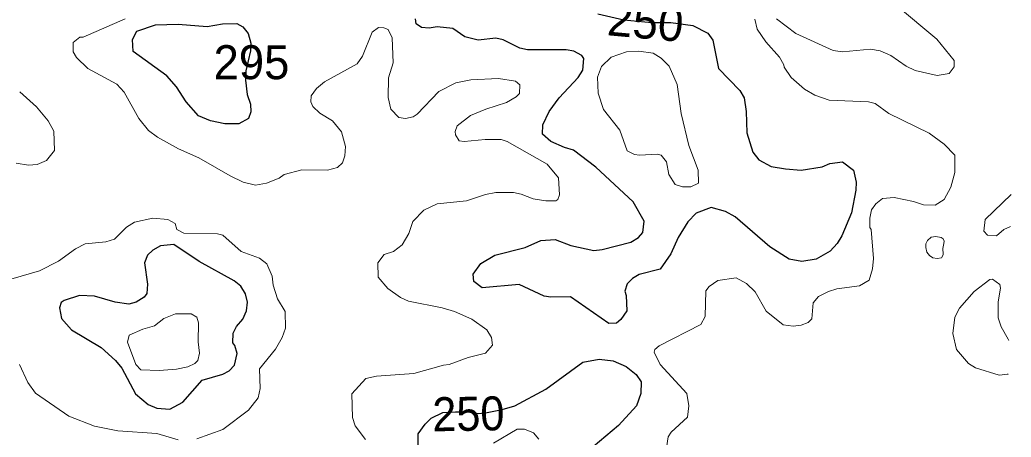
# Model space of a CAD drawing. Extents: x 763.2 to 816.8, y 7896.5 to 7952.7.
# Drawn here: x 811.377 to 816.045, y 7905.868 to 7907.832 of the extents above; entities that cross this region are included whole.
import ezdxf
from ezdxf.enums import TextEntityAlignment as Align

# ---------------------------------------------------------------- set-up
doc = ezdxf.new("R2010")
doc.units = 0
doc.header["$LTSCALE"] = 0.064
doc.layers.add('1', color=7, linetype='Continuous', lineweight=25)
doc.layers.add('2', color=7, linetype='Continuous', lineweight=13)
doc.layers.add('21', color=7, linetype='Continuous')
doc.layers.add('61', color=7, linetype='Continuous')

msp = doc.modelspace()

# ---------------------------------------------------------------- linework, layer by layer
at = {"layer": '1'}
for points in [[(815.1546, 7907.1394), (815.1905, 7907.156), (815.2505, 7907.164), (815.3026, 7907.1252), (815.3146, 7907.068), (815.3129, 7907.0303), (815.2921, 7906.9243), (815.2477, 7906.8148), (815.2254, 7906.7791), (815.193, 7906.7436), (815.1264, 7906.706), (815.0592, 7906.6943), (815, 7906.7063), (814.9089, 7906.7636), (814.7444, 7906.9045), (814.7, 7906.9307), (814.6327, 7906.9487), (814.5617, 7906.9216), (814.5226, 7906.8815), (814.4766, 7906.8075), (814.4424, 7906.7304), (814.3918, 7906.659), (814.2935, 7906.6329), (814.2614, 7906.6152), (814.2359, 7906.5899), (814.2254, 7906.5552), (814.2316, 7906.5349), (814.2347, 7906.4625), (814.2064, 7906.4211), (814.1859, 7906.4047), (814.1495, 7906.4035), (813.9702, 7906.5279), (813.8768, 7906.5266), (813.8448, 7906.5322), (813.7271, 7906.5857), (813.554, 7906.5714), (813.5151, 7906.5998), (813.5105, 7906.6358), (813.5478, 7906.6857), (813.6131, 7906.725), (813.7567, 7906.7611), (813.8299, 7906.794), (813.8977, 7906.7974), (813.9713, 7906.77), (814.0798, 7906.7469), (814.1182, 7906.7504), (814.2531, 7906.7858), (814.2898, 7906.8071), (814.3106, 7906.8315), (814.3169, 7906.8846), (814.2647, 7906.9754), (814.0892, 7907.139), (813.9831, 7907.2187), (813.9408, 7907.2306), (813.8762, 7907.2597), (813.8377, 7907.2942), (813.8395, 7907.3383), (813.8691, 7907.401), (813.9167, 7907.4655), (814.0053, 7907.5606), (814.0273, 7907.5958), (814.0328, 7907.6507), (814.0236, 7907.6647), (813.9858, 7907.6847), (813.949, 7907.6901), (813.7675, 7907.6903), (813.7305, 7907.699), (813.6532, 7907.7376), (813.6178, 7907.7457), (813.5349, 7907.7363), (813.4714, 7907.7525), (813.4163, 7907.7905), (813.3417, 7907.7984), (813.3047, 7907.7921), (813.268, 7907.7957), (813.2422, 7907.8133), (813.239, 7907.837)], [(814.0977, 7907.8609), (814.2211, 7907.8314), (814.3532, 7907.8196), (814.4415, 7907.8194), (814.545, 7907.8057)], [(814.545, 7907.8057), (814.617, 7907.7692), (814.6393, 7907.7369), (814.6658, 7907.6031), (814.7669, 7907.4999), (814.7872, 7907.4642)], [(814.7872, 7907.4642), (814.7968, 7907.4009), (814.8004, 7907.2999), (814.8275, 7907.2091), (814.8563, 7907.1726), (814.9137, 7907.1424), (814.9813, 7907.13), (815.056, 7907.1249), (815.1546, 7907.1394)], [(813.252, 7905.8034), (813.2527, 7905.8844), (813.285, 7905.9298), (813.3142, 7905.9574), (813.3692, 7905.9836), (813.4279, 7905.9878), (813.4839, 7905.9865), (813.5386, 7905.9789), (813.5768, 7905.984), (813.6474, 7905.9979), (813.7069, 7906.0154), (813.8531, 7906.0939), (814.0273, 7906.2204), (814.1043, 7906.2355), (814.1699, 7906.2271), (814.231, 7906.2012), (814.2793, 7906.1633), (814.3023, 7906.1288), (814.3007, 7906.073), (814.28, 7906.0148), (814.1959, 7905.9223), (814.076, 7905.8218)]]:
    msp.add_lwpolyline(points, dxfattribs=at)
for points in [[(812.1223, 7907.8115), (812.2595, 7907.8002), (812.3302, 7907.8134), (812.398, 7907.8146), (812.4266, 7907.7989), (812.4513, 7907.7679), (812.4646, 7907.7229), (812.4634, 7907.6859), (812.4415, 7907.5925), (812.4387, 7907.5484), (812.4469, 7907.4804), (812.4629, 7907.4344), (812.4645, 7907.3997), (812.4539, 7907.3684), (812.4071, 7907.3431), (812.3425, 7907.3429), (812.275, 7907.3566), (812.2173, 7907.3803), (812.1594, 7907.4453), (812.1148, 7907.5166), (812.0682, 7907.5692), (811.9103, 7907.6832), (811.9073, 7907.7399), (811.9279, 7907.7787), (812.0147, 7907.8081)], [(812.4485, 7906.5025), (812.4399, 7906.542), (812.4167, 7906.578), (812.386, 7906.6037), (812.2208, 7906.6953), (812.1022, 7906.7745), (812.0387, 7906.7676), (812.0026, 7906.7478), (811.9771, 7906.7252), (811.9639, 7906.6885), (811.9784, 7906.5873), (811.9751, 7906.5436), (811.9614, 7906.5262), (811.925, 7906.504), (811.8898, 7906.4939), (811.8258, 7906.5036), (811.7277, 7906.5312), (811.6581, 7906.5347), (811.5852, 7906.5113), (811.5708, 7906.501), (811.563, 7906.4772), (811.5729, 7906.4265), (811.6202, 7906.3737), (811.7593, 7906.2903), (811.8269, 7906.2292), (811.8577, 7906.193), (811.921, 7906.0716), (811.9808, 7906.0211), (812.0213, 7906.0037), (812.0837, 7905.999), (812.1449, 7906.0323), (812.2356, 7906.1356), (812.3325, 7906.1637), (812.3629, 7906.1799), (812.3871, 7906.2072), (812.4006, 7906.2622), (812.3891, 7906.2996), (812.3791, 7906.3122), (812.3813, 7906.3572), (812.3965, 7906.389), (812.4274, 7906.4237), (812.4436, 7906.4631)]]:
    msp.add_lwpolyline(points, close=True, dxfattribs=at)
at = {"layer": '2'}
for points in [[(815.5054, 7907.8989), (815.6938, 7907.7415), (815.7764, 7907.6401), (815.7764, 7907.6104), (815.7521, 7907.5789), (815.6956, 7907.5702), (815.5931, 7907.5929), (815.5502, 7907.6147), (815.4776, 7907.6645), (815.4283, 7907.6866), (815.3828, 7907.6932), (815.2497, 7907.682), (815.2066, 7907.6872), (815.0311, 7907.767), (814.9402, 7907.8368)], [(813.2785, 7906.9355), (813.342, 7906.9665), (813.4795, 7906.9802), (813.5691, 7907.0099), (813.6177, 7907.0195), (813.7014, 7907.0191), (813.7377, 7907.0122), (813.7939, 7906.9902), (813.8538, 7906.9802), (813.9002, 7906.9802), (813.9102, 7906.9865), (813.9177, 7907.0087), (813.9128, 7907.089), (813.8596, 7907.1529), (813.6709, 7907.2592), (813.6426, 7907.2689), (813.5677, 7907.2693), (813.4691, 7907.2595), (813.4446, 7907.2633), (813.4282, 7907.2908), (813.4266, 7907.3068), (813.4366, 7907.3333), (813.4992, 7907.3815), (813.5711, 7907.4123), (813.6683, 7907.443), (813.7139, 7907.4702), (813.7287, 7907.486), (813.7317, 7907.5265), (813.7109, 7907.5433), (813.6301, 7907.5553), (813.4998, 7907.5492), (813.4298, 7907.5354), (813.3497, 7907.4949), (813.2473, 7907.3877), (813.2288, 7907.3754), (813.1921, 7907.3681), (813.1606, 7907.3718), (813.1241, 7907.4108), (813.111, 7907.467), (813.1123, 7907.5588), (813.1338, 7907.63), (813.1304, 7907.7476), (813.1106, 7907.7867), (813.091, 7907.795), (813.0658, 7907.7952), (813.0354, 7907.7738), (812.9905, 7907.6615), (812.965, 7907.625), (812.8105, 7907.5397), (812.7731, 7907.5085), (812.7478, 7907.4741), (812.7462, 7907.4453), (812.7556, 7907.4242), (812.7899, 7907.3934), (812.8484, 7907.3559), (812.8912, 7907.3052), (812.9102, 7907.2365), (812.9069, 7907.1915), (812.8955, 7907.1594), (812.8731, 7907.1375), (812.8249, 7907.1248), (812.704, 7907.1263), (812.6212, 7907.1033), (812.5974, 7907.087), (812.5376, 7907.0635), (812.4859, 7907.0542), (812.4279, 7907.0686), (812.3674, 7907.0971), (812.2201, 7907.1822), (812.1237, 7907.2246), (812.0251, 7907.2805), (811.9823, 7907.3115), (811.9366, 7907.3684), (811.8684, 7907.4912), (811.8334, 7907.5294), (811.6965, 7907.6026), (811.6427, 7907.6544), (811.628, 7907.6809), (811.6281, 7907.7246), (811.6599, 7907.7506), (811.6753, 7907.7511), (811.8724, 7907.8365)], [(814.8381, 7907.8355), (814.8487, 7907.7874), (814.8891, 7907.7284), (814.9531, 7907.6555), (814.9741, 7907.6207), (814.9753, 7907.6086), (815.0086, 7907.5609), (815.0712, 7907.5052), (815.1198, 7907.4778), (815.1875, 7907.4538), (815.3733, 7907.4468), (815.4044, 7907.4386), (815.4682, 7907.3906), (815.6589, 7907.2986), (815.7294, 7907.2474), (815.7792, 7907.1958), (815.7795, 7907.1134), (815.76, 7907.0442), (815.7293, 7906.9858)], [(811.3762, 7907.4936), (811.4553, 7907.4227), (811.5096, 7907.3572), (811.5364, 7907.308), (811.5398, 7907.2166), (811.5015, 7907.1693), (811.4586, 7907.1514), (811.4181, 7907.1478), (811.3589, 7907.1576)], [(815.4386, 7906.9916), (815.4079, 7906.9663), (815.3872, 7906.9372), (815.3788, 7906.8989), (815.3788, 7906.8551), (815.3853, 7906.8456), (815.3969, 7906.7092), (815.392, 7906.6603), (815.3752, 7906.6073), (815.3304, 7906.5799), (815.2244, 7906.5658), (815.1842, 7906.5541), (815.1367, 7906.5303), (815.1128, 7906.5), (815.106, 7906.4245), (815.0884, 7906.4068), (815.0553, 7906.3948), (815.0179, 7906.3902), (814.9706, 7906.3964), (814.8902, 7906.4613), (814.8392, 7906.5515), (814.7976, 7906.5917), (814.7496, 7906.6182), (814.6629, 7906.6056), (814.6224, 7906.5769), (814.6064, 7906.5563), (814.6036, 7906.4353), (814.5829, 7906.3987), (814.3874, 7906.2972), (814.3665, 7906.2807), (814.3636, 7906.2674), (814.3918, 7906.2096), (814.5177, 7906.074), (814.5273, 7906.0154), (814.5209, 7905.9622), (814.4433, 7905.8914), (814.429, 7905.87), (814.4223, 7905.8173)], [(815.7293, 7906.9858), (815.6874, 7906.9592), (815.6313, 7906.9606), (815.5851, 7906.977), (815.4931, 7906.9965), (815.4386, 7906.9916)], [(816.0421, 7906.859), (816.0099, 7906.845), (815.9756, 7906.8162), (815.9334, 7906.8183), (815.9151, 7906.837), (815.9224, 7906.8916), (816.0444, 7907.0097), (816.0446, 7907.0099)], [(812.2093, 7905.8599), (812.3324, 7905.9041), (812.4528, 7905.9951), (812.4993, 7906.0525), (812.5076, 7906.0977), (812.505, 7906.1889), (812.5807, 7906.282), (812.6121, 7906.3366), (812.6275, 7906.3803), (812.6262, 7906.4596), (812.5896, 7906.519), (812.5688, 7906.5834), (812.5648, 7906.6249), (812.54, 7906.6831), (812.5055, 7906.7101), (812.4194, 7906.741), (812.3322, 7906.8192), (812.3081, 7906.8256), (812.1493, 7906.8287), (812.1156, 7906.8452), (812.1076, 7906.8734), (812.0741, 7906.8923), (812.0025, 7906.8978), (811.9172, 7906.8794), (811.8788, 7906.8556), (811.8217, 7906.7993), (811.7822, 7906.7878), (811.6843, 7906.7779), (811.6384, 7906.7549), (811.5588, 7906.6955), (811.4688, 7906.6504), (811.335, 7906.6121)], [(813.0917, 7906.7269), (813.1367, 7906.7418), (813.1765, 7906.7731), (813.2086, 7906.826), (813.2274, 7906.8831), (813.2785, 7906.9355)], [(813.0044, 7905.857), (812.9559, 7905.9215), (812.9432, 7905.9602), (812.9402, 7906.0722), (813.0053, 7906.1437), (813.0556, 7906.1551), (813.2317, 7906.1682), (813.3715, 7906.2075), (813.3989, 7906.2092), (813.4875, 7906.2433), (813.5687, 7906.2635), (813.6019, 7906.3015), (813.5977, 7906.3362), (813.5749, 7906.3723), (813.5052, 7906.4229), (813.4237, 7906.4589), (813.3655, 7906.4772), (813.2068, 7906.5082), (813.1696, 7906.5258), (813.1097, 7906.5673), (813.0647, 7906.6209), (813.0616, 7906.688), (813.0917, 7906.7269)], [(816.0303, 7906.1654), (816.0289, 7906.1652), (815.988, 7906.1597), (815.8768, 7906.1939), (815.8437, 7906.215), (815.7868, 7906.2811), (815.77, 7906.3557), (815.7796, 7906.4321), (815.8017, 7906.4752), (815.8699, 7906.5538), (815.9441, 7906.6101), (815.9565, 7906.6117), (815.9919, 7906.5858), (815.9948, 7906.5685), (815.9834, 7906.5052), (815.9837, 7906.4296), (815.9978, 7906.3879), (816.0297, 7906.3293), (816.033, 7906.3233)], [(811.3752, 7906.2092), (811.4141, 7906.1253), (811.4505, 7906.0753), (811.6081, 7905.9665), (811.7275, 7905.919), (811.8382, 7905.8971), (812.0222, 7905.8855), (812.1216, 7905.8561)], [(813.8205, 7905.8591), (813.7951, 7905.8878), (813.7525, 7905.9051), (813.7186, 7905.9049), (813.6064, 7905.8398)]]:
    msp.add_lwpolyline(points, dxfattribs=at)
for points in [[(814.3769, 7907.2002), (814.3966, 7907.1948), (814.4215, 7907.1638), (814.4323, 7907.1041), (814.4619, 7907.0575), (814.4965, 7907.0462), (814.5366, 7907.0459), (814.5716, 7907.063), (814.5707, 7907.1243), (814.5261, 7907.2408), (814.4909, 7907.3916), (814.4715, 7907.5274), (814.4345, 7907.6135), (814.3961, 7907.6522), (814.3591, 7907.6758), (814.2908, 7907.6851), (814.2339, 7907.6818), (814.1614, 7907.6564), (814.1161, 7907.6129), (814.097, 7907.5629), (814.1005, 7907.4868), (814.1247, 7907.4097), (814.2018, 7907.3124), (814.2366, 7907.2155), (814.2705, 7907.1989), (814.2949, 7907.1946)], [(815.6482, 7906.7391), (815.6421, 7906.7598), (815.6421, 7906.7783), (815.651, 7906.7928), (815.6679, 7906.809), (815.6901, 7906.813), (815.7149, 7906.8083), (815.7244, 7906.8009), (815.7286, 7906.7904), (815.7271, 7906.7791), (815.724, 7906.7636), (815.7224, 7906.7564), (815.7224, 7906.749), (815.7251, 7906.7351), (815.7251, 7906.7253), (815.7172, 7906.7124), (815.6959, 7906.7084), (815.6759, 7906.7121), (815.6607, 7906.7235)], [(812.168, 7906.1997), (812.2007, 7906.2141), (812.2145, 7906.2287), (812.2233, 7906.2626), (812.2169, 7906.3172), (812.2183, 7906.4065), (812.2099, 7906.4326), (812.1837, 7906.4491), (812.109, 7906.4491), (812.0542, 7906.4262), (812.0112, 7906.392), (811.9558, 7906.3764), (811.8914, 7906.3482), (811.8832, 7906.3152), (811.9236, 7906.2106), (811.9463, 7906.1847), (812.0321, 7906.1815), (812.1136, 7906.1878)]]:
    msp.add_lwpolyline(points, close=True, dxfattribs=at)

# ---------------------------------------------------------------- texts
at = {"layer": '21'}
msp.add_text('295', height=0.16, dxfattribs=at).set_placement((812.2888, 7907.5526))
at = {"layer": '61'}
msp.add_text('250', height=0.16, rotation=354.828, dxfattribs=at).set_placement((814.3161, 7907.7439), align=Align.CENTER)
at = {"layer": '61', "width": 0.95}
msp.add_text('250', height=0.16, rotation=0.947, dxfattribs=at).set_placement((813.4899, 7905.898), align=Align.CENTER)

doc.saveas('drawing.dxf')
